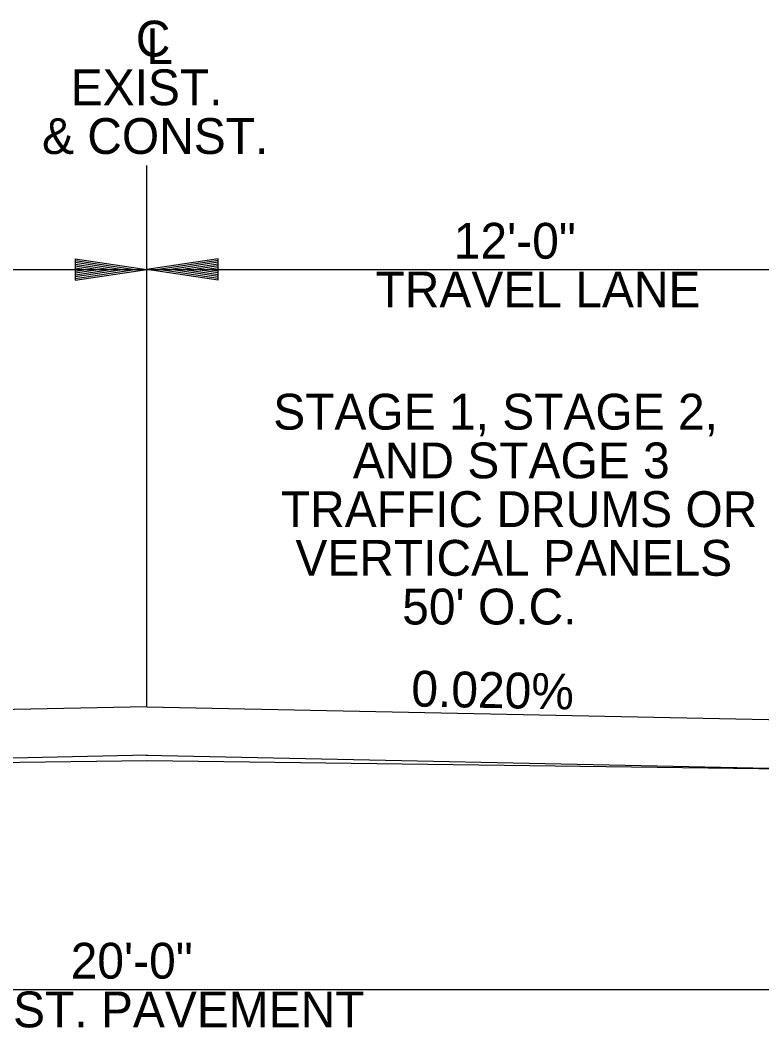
# Model space of a CAD drawing. Extents: x 6125 to 14104, y 8730 to 11067.
# Drawn here: x 8970 to 9177, y 10462.8 to 10744.1 of the extents above; entities that cross this region are included whole.
import ezdxf

# ---------------------------------------------------------------- set-up
doc = ezdxf.new("R2010")
doc.units = 0
doc.layers.add('R_No Plot', color=7, linetype='Continuous')
doc.layers.add('Stage 1 Construction', color=7, linetype='Continuous')

msp = doc.modelspace()

# ---------------------------------------------------------------- linework, layer by layer
for p, q in [((9005.34, 10552.42), (8791.5, 10548.14)), ((9005.34, 10552.42), (9219.18, 10548.14)), ((9005.61, 10538.92), (8811.77, 10534.91)), ((9005.07, 10538.92), (9198.91, 10534.91))]:
    msp.add_line(p, q)
at = {"layer": 'R_No Plot'}
msp.add_lwpolyline([(8214.89, 10518), (8254.65, 10519.44), (8315.6, 10518.95), (8407.69, 10512.22), (8460.38, 10505.08), (8509.6, 10474.31), (8577.8, 10476.49), (8706.53, 10525.21), (8791.77, 10534.65), (9005.58, 10537.5), (9218.91, 10534.65), (9305.32, 10526.21), (9403.95, 10495.87), (9428.25, 10465.26), (9480.75, 10463.74), (9510.7, 10505.46), (9538.9, 10523.87), (9588.81, 10533.21), (9678.01, 10524.64), (9750.81, 10523.3)], dxfattribs=at)
at = {"layer": 'Stage 1 Construction'}
for p, q in [((9005.34, 10552.42), (9005.34, 10703.53)), ((8985.34, 10677.54), (9005.34, 10674.54)), ((8985.34, 10677.54), (8985.34, 10671.54)), ((8985.34, 10677.04), (9002, 10674.54)), ((8985.34, 10676.53), (8998.56, 10674.54)), ((8985.34, 10676.03), (8995.23, 10674.54)), ((8985.34, 10675.51), (8991.84, 10674.54)), ((9025.34, 10677.54), (9005.34, 10674.54)), ((9025.34, 10677.04), (9008.68, 10674.54)), ((9025.34, 10676.53), (9012.12, 10674.54)), ((9025.34, 10676.03), (9015.45, 10674.54)), ((9025.34, 10675.52), (9018.84, 10674.54)), ((9025.34, 10671.54), (9025.34, 10677.54)), ((8791.5, 10674.54), (9005.34, 10674.54)), ((8985.34, 10675.01), (8988.5, 10674.54)), ((8985.34, 10671.54), (9005.34, 10674.54)), ((8985.34, 10673.56), (8991.84, 10674.54)), ((8985.34, 10672.55), (8998.56, 10674.54)), ((8985.34, 10672.04), (9002, 10674.54)), ((8985.34, 10673.05), (8995.23, 10674.54)), ((8985.34, 10674.07), (8988.5, 10674.54)), ((9005.34, 10674.54), (9219.18, 10674.54)), ((9025.34, 10671.54), (9005.34, 10674.54)), ((9025.34, 10672.04), (9008.68, 10674.54)), ((9025.34, 10672.55), (9012.12, 10674.54)), ((9025.34, 10673.05), (9015.45, 10674.54)), ((9025.34, 10673.57), (9018.84, 10674.54)), ((9025.34, 10675.01), (9022.18, 10674.54)), ((9025.34, 10674.07), (9022.18, 10674.54)), ((8811.77, 10473.57), (9198.91, 10473.57))]:
    msp.add_line(p, q, dxfattribs=at)

# ---------------------------------------------------------------- texts
for s, p in [('C', (9002.3, 10733.98)), ('L', (9005.26, 10731.88)), ('EXIST.', (8984.14, 10720.38)), ('& CONST.', (8976.14, 10706.78)), ('12\'-0"', (9091.06, 10677.54)), ('TRAVEL LANE', (9069.22, 10663.94)), ('STAGE 1, STAGE 2,', (9040.66, 10629.83)), ('AND STAGE 3', (9062.88, 10616.23)), ('TRAFFIC DRUMS OR', (9042.79, 10602.63)), ('VERTICAL PANELS', (9046.86, 10589.03)), ("50' O.C.", (9076.66, 10575.43)), ('20\'-0"', (8984.14, 10476.57)), ('EXIST. PAVEMENT', (8946.51, 10462.97))]:
    msp.add_text(s, height=10, dxfattribs=at).set_placement(p)
msp.add_text('0.020%', height=10, rotation=358.8777, dxfattribs=at).set_placement((9079.14, 10552.56))

doc.saveas('drawing.dxf')
